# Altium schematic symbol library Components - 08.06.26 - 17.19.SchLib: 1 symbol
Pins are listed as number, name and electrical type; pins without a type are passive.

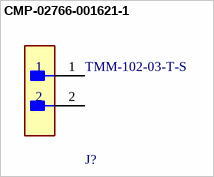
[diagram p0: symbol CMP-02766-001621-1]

## CMP-02766-001621-1
designator J?, comment TMM-102-03-T-S
CONN HEADER VERT 2POS 2MM; Max Voltage Rating (AC): 500V; Gender: Male; Number of Positions: 2; Max Current Rating: 3.9A
footprint FP-TMM-102-03-T-S-MFG
pins: 1, 2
